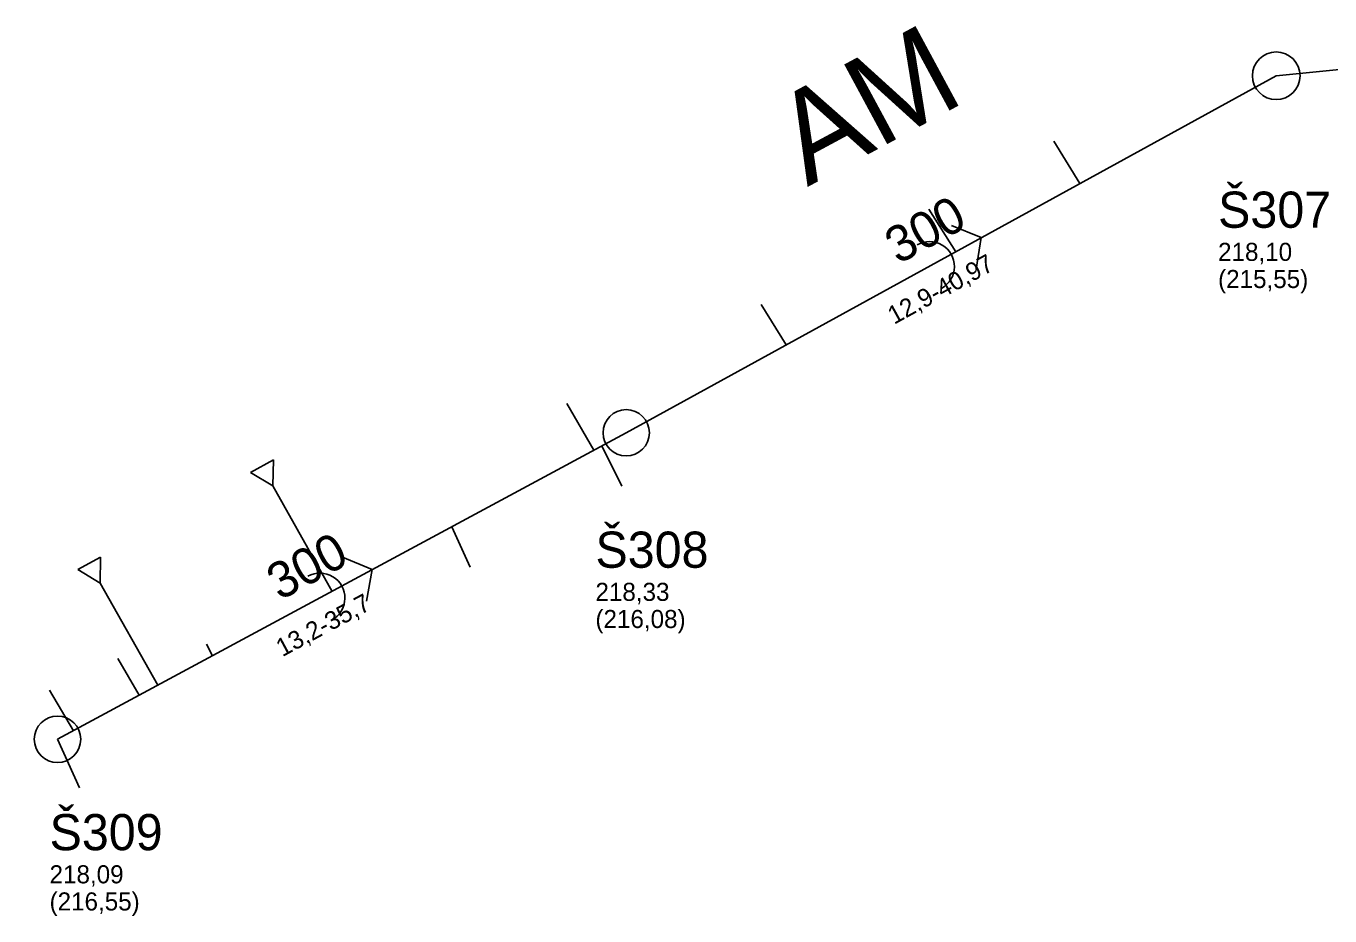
# Model space of a CAD drawing. Extents: x -574467 to -573663, y -1191209 to -1190406.
# Drawn here: x -574244.6 to -574172.6, y -1190627.4 to -1190578.2 of the extents above; entities that cross this region are included whole.
import ezdxf

# ---------------------------------------------------------------- set-up
doc = ezdxf.new("R2010")
doc.units = 0
for name, color, linetype in [('Vrstva 1', 7, 'Continuous'), ('Vrstva 12', 7, 'Continuous'), ('Vrstva 15', 7, 'Continuous'), ('Vrstva 29', 7, 'Continuous'), ('Vrstva 35', 7, 'Continuous'), ('Vrstva 41', 7, 'Continuous'), ('Vrstva 44', 7, 'Continuous'), ('Vrstva 45', 7, 'Continuous'), ('Vrstva 56', 7, 'Continuous'), ('Vrstva 57', 7, 'Continuous')]:
    doc.layers.add(name, color=color, linetype=linetype)

# ---------------------------------------------------------------- blocks, each defined once
blk = doc.blocks.new('100')
at = {"layer": 'Vrstva 1'}
blk.add_circle((0, 0), 1.27, dxfattribs=at)
blk = doc.blocks.new('106')
at = {"layer": 'Vrstva 1'}
for p, q in [((1.25, 0.72), (0, 0)), ((0, 0), (1.25, -0.72)), ((1.25, -0.72), (1.25, 0.72))]:
    blk.add_line(p, q, dxfattribs=at)
blk = doc.blocks.new('91')
at = {"layer": 'Vrstva 1'}
blk.add_lwpolyline([(0.79, 1.37), (1.89, 0), (0.79, -1.38)], dxfattribs=at)
blk.add_arc((-1.372, 0), 1.372, 270, 90, dxfattribs=at)

msp = doc.modelspace()

# ---------------------------------------------------------------- linework, layer by layer
at = {"layer": 'Vrstva 12'}
for p, q in [((-574186.414, -1190586.938), (-574187.854, -1190584.602)), ((-574193.277, -1190590.709), (-574194.756, -1190588.355)), ((-574202.646, -1190595.856), (-574204.018, -1190593.622)), ((-574213.263, -1190601.671), (-574214.754, -1190599.091)), ((-574212.832, -1190601.439), (-574211.729, -1190603.663)), ((-574227.734, -1190609.473), (-574230.997, -1190603.645)), ((-574221.106, -1190605.9), (-574220.109, -1190608.145)), ((-574237.363, -1190614.665), (-574240.545, -1190609.017)), ((-574234.344, -1190613.037), (-574234.662, -1190612.394)), ((-574238.384, -1190615.215), (-574239.575, -1190613.176)), ((-574242.02, -1190617.175), (-574243.338, -1190614.927)), ((-574242.9, -1190617.65), (-574241.694, -1190620.34))]:
    msp.add_line(p, q, dxfattribs=at)
at = {"layer": 'Vrstva 15'}
for p, q in [((-574175.57, -1190580.98), (-574163.15, -1190579.76)), ((-574211.48, -1190600.71), (-574175.57, -1190580.98)), ((-574242.9, -1190617.65), (-574211.48, -1190600.71))]:
    msp.add_line(p, q, dxfattribs=at)

# ---------------------------------------------------------------- block references
at = {"layer": 'Vrstva 12', "xscale": 0.999999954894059, "yscale": 0.9999999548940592, "rotation": 119.00000058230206}
for p in [(-574230.997, -1190603.645), (-574240.545, -1190609.017)]:
    msp.add_blockref('106', p, dxfattribs=at)
at = {"layer": 'Vrstva 29'}
for p, xscale, yscale, rotation in [((-574175.57, -1190580.98), 1.0365458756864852, 1.0365458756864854, -158.02850914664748), ((-574211.48, -1190600.71), 1.0072562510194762, 1.0072562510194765, -151.23333635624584), ((-574242.9, -1190617.65), 1.0106517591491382, 1.010651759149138, -151.83788415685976)]:
    msp.add_blockref('100', p, dxfattribs=dict(at, xscale=xscale, yscale=yscale, rotation=rotation))
at = {"layer": 'Vrstva 41'}
for p, xscale, yscale, rotation in [((-574193.525, -1190590.845), 1.0037041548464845, 1.0037041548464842, 29.379208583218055), ((-574227.19, -1190609.18), 1.0072562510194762, 1.0072562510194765, 28.766663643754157)]:
    msp.add_blockref('91', p, dxfattribs=dict(at, xscale=xscale, yscale=yscale, rotation=rotation))

# ---------------------------------------------------------------- texts
at = {"layer": 'Vrstva 35'}
msp.add_text('AM', height=5, rotation=28.33, dxfattribs=at).set_placement((-574201.47, -1190587.132))
at = {"layer": 'Vrstva 44'}
for rotation, p in [(28.79, (-574196.453, -1190591.426)), (28.33, (-574230.62, -1190610.006))]:
    msp.add_text('300', height=2, rotation=rotation, dxfattribs=at).set_placement(p)
at = {"layer": 'Vrstva 45'}
for s, rotation, p in [('12,9-40,97', 28.79, (-574196.68, -1190594.745)), ('13,2-35,7', 28.33, (-574230.479, -1190613.115))]:
    msp.add_text(s, height=1, rotation=rotation, dxfattribs=at).set_placement(p)
at = {"layer": 'Vrstva 56'}
for s, p in [('218,10 ', (-574178.78, -1190591.21)), ('(215,55)', (-574178.78, -1190592.71)), ('218,33 ', (-574213.18, -1190610)), ('(216,08)', (-574213.18, -1190611.5)), ('218,09 ', (-574243.34, -1190625.61)), ('(216,55)', (-574243.34, -1190627.11))]:
    msp.add_text(s, height=1, dxfattribs=at).set_placement(p)
at = {"layer": 'Vrstva 57'}
for s, p in [('Š307', (-574178.78, -1190589.38)), ('Š308', (-574213.18, -1190608.17)), ('Š309', (-574243.34, -1190623.78))]:
    msp.add_text(s, height=2, dxfattribs=at).set_placement(p)

doc.saveas('drawing.dxf')
